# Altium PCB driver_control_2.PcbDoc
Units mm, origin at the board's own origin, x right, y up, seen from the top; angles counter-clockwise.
Board outline 75 x 80 mm, 2 copper layers (Top Layer, Bottom Layer); 60 components, 54 nets, 275 pads, 69 vias.
Unrouted connection lines stored in the file: 1.
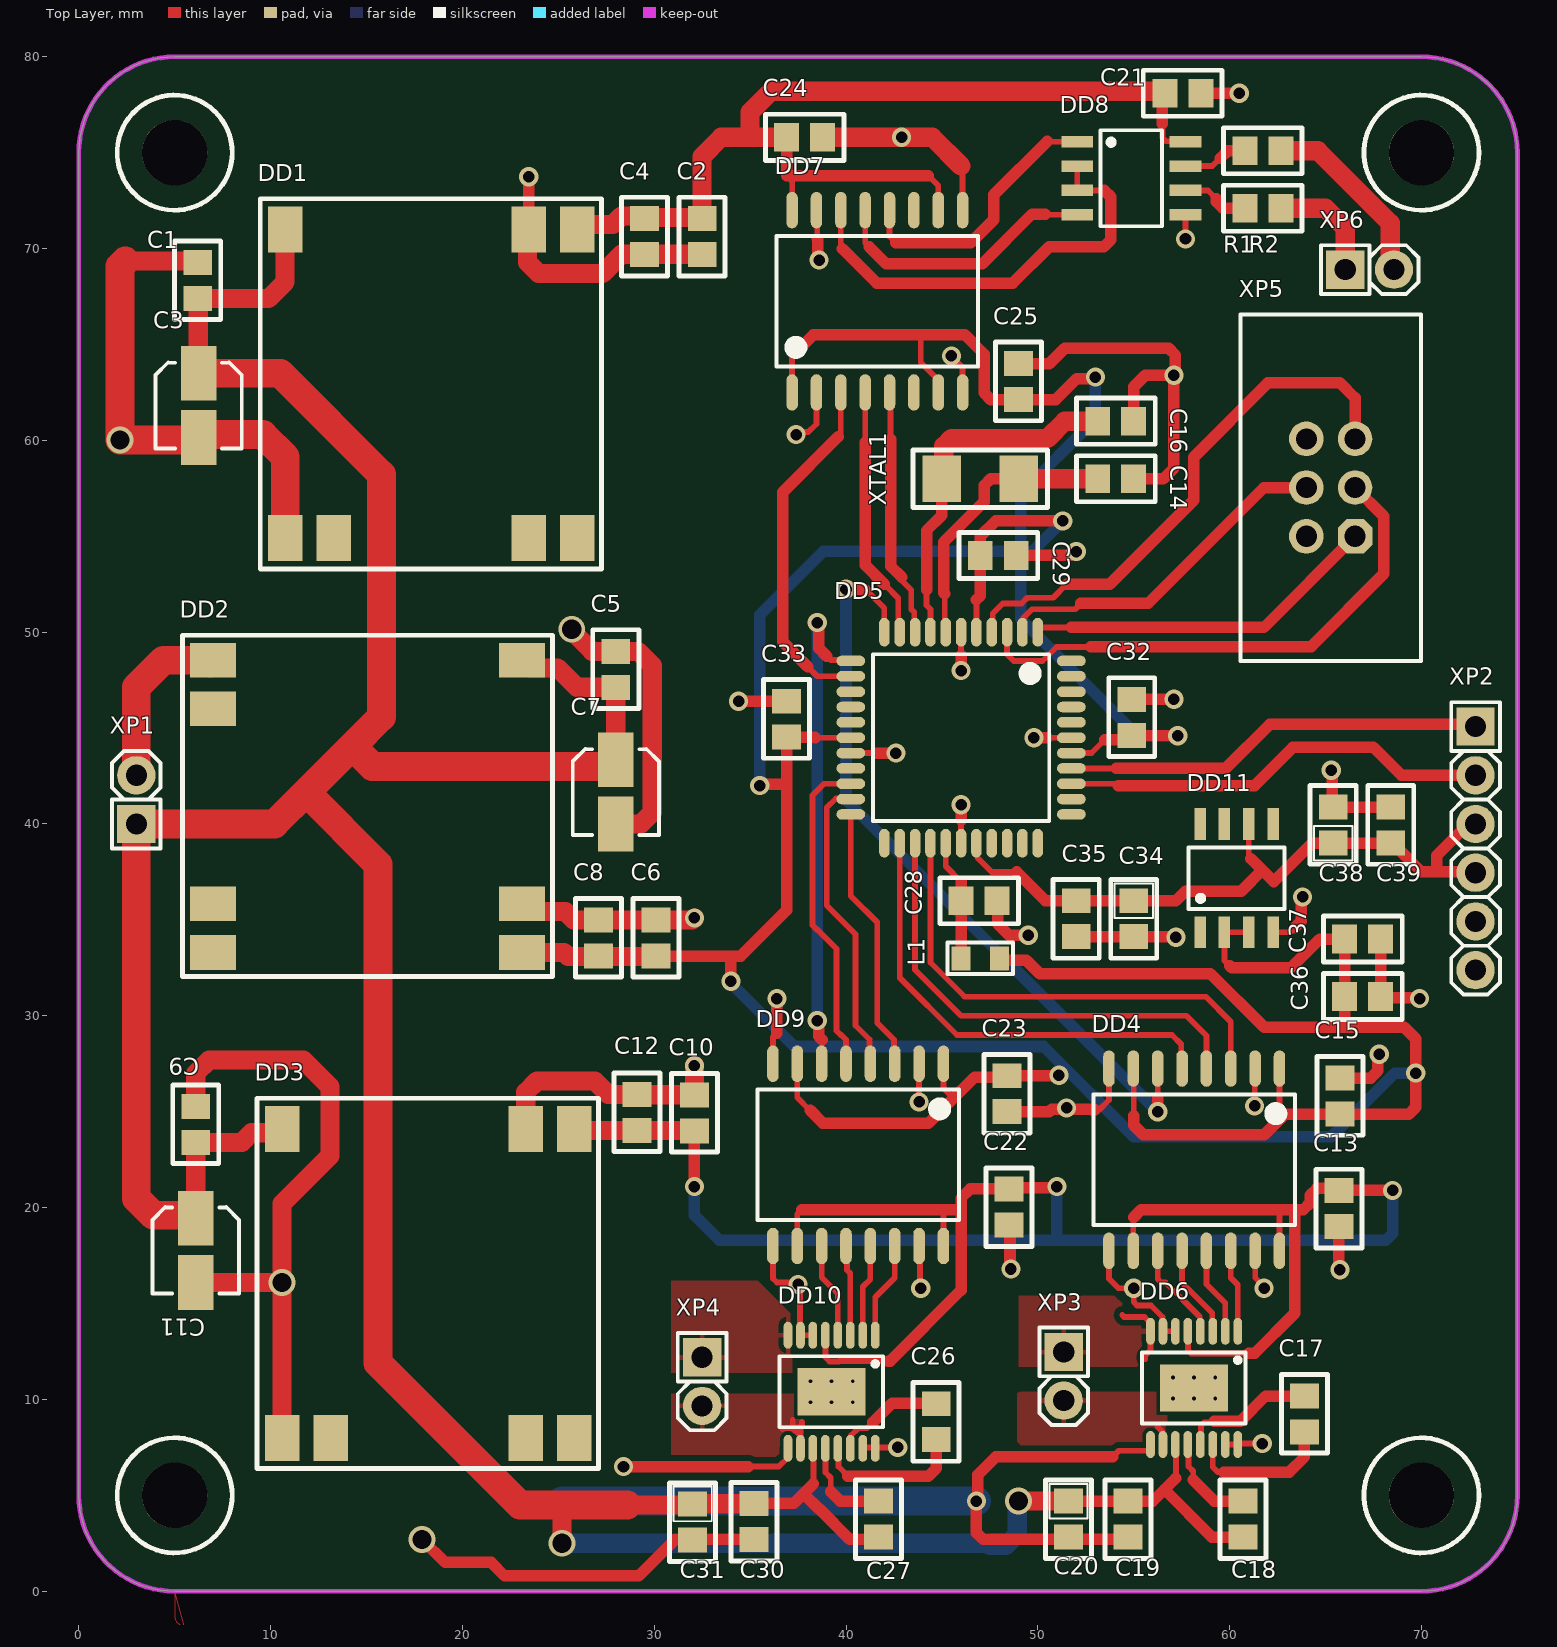
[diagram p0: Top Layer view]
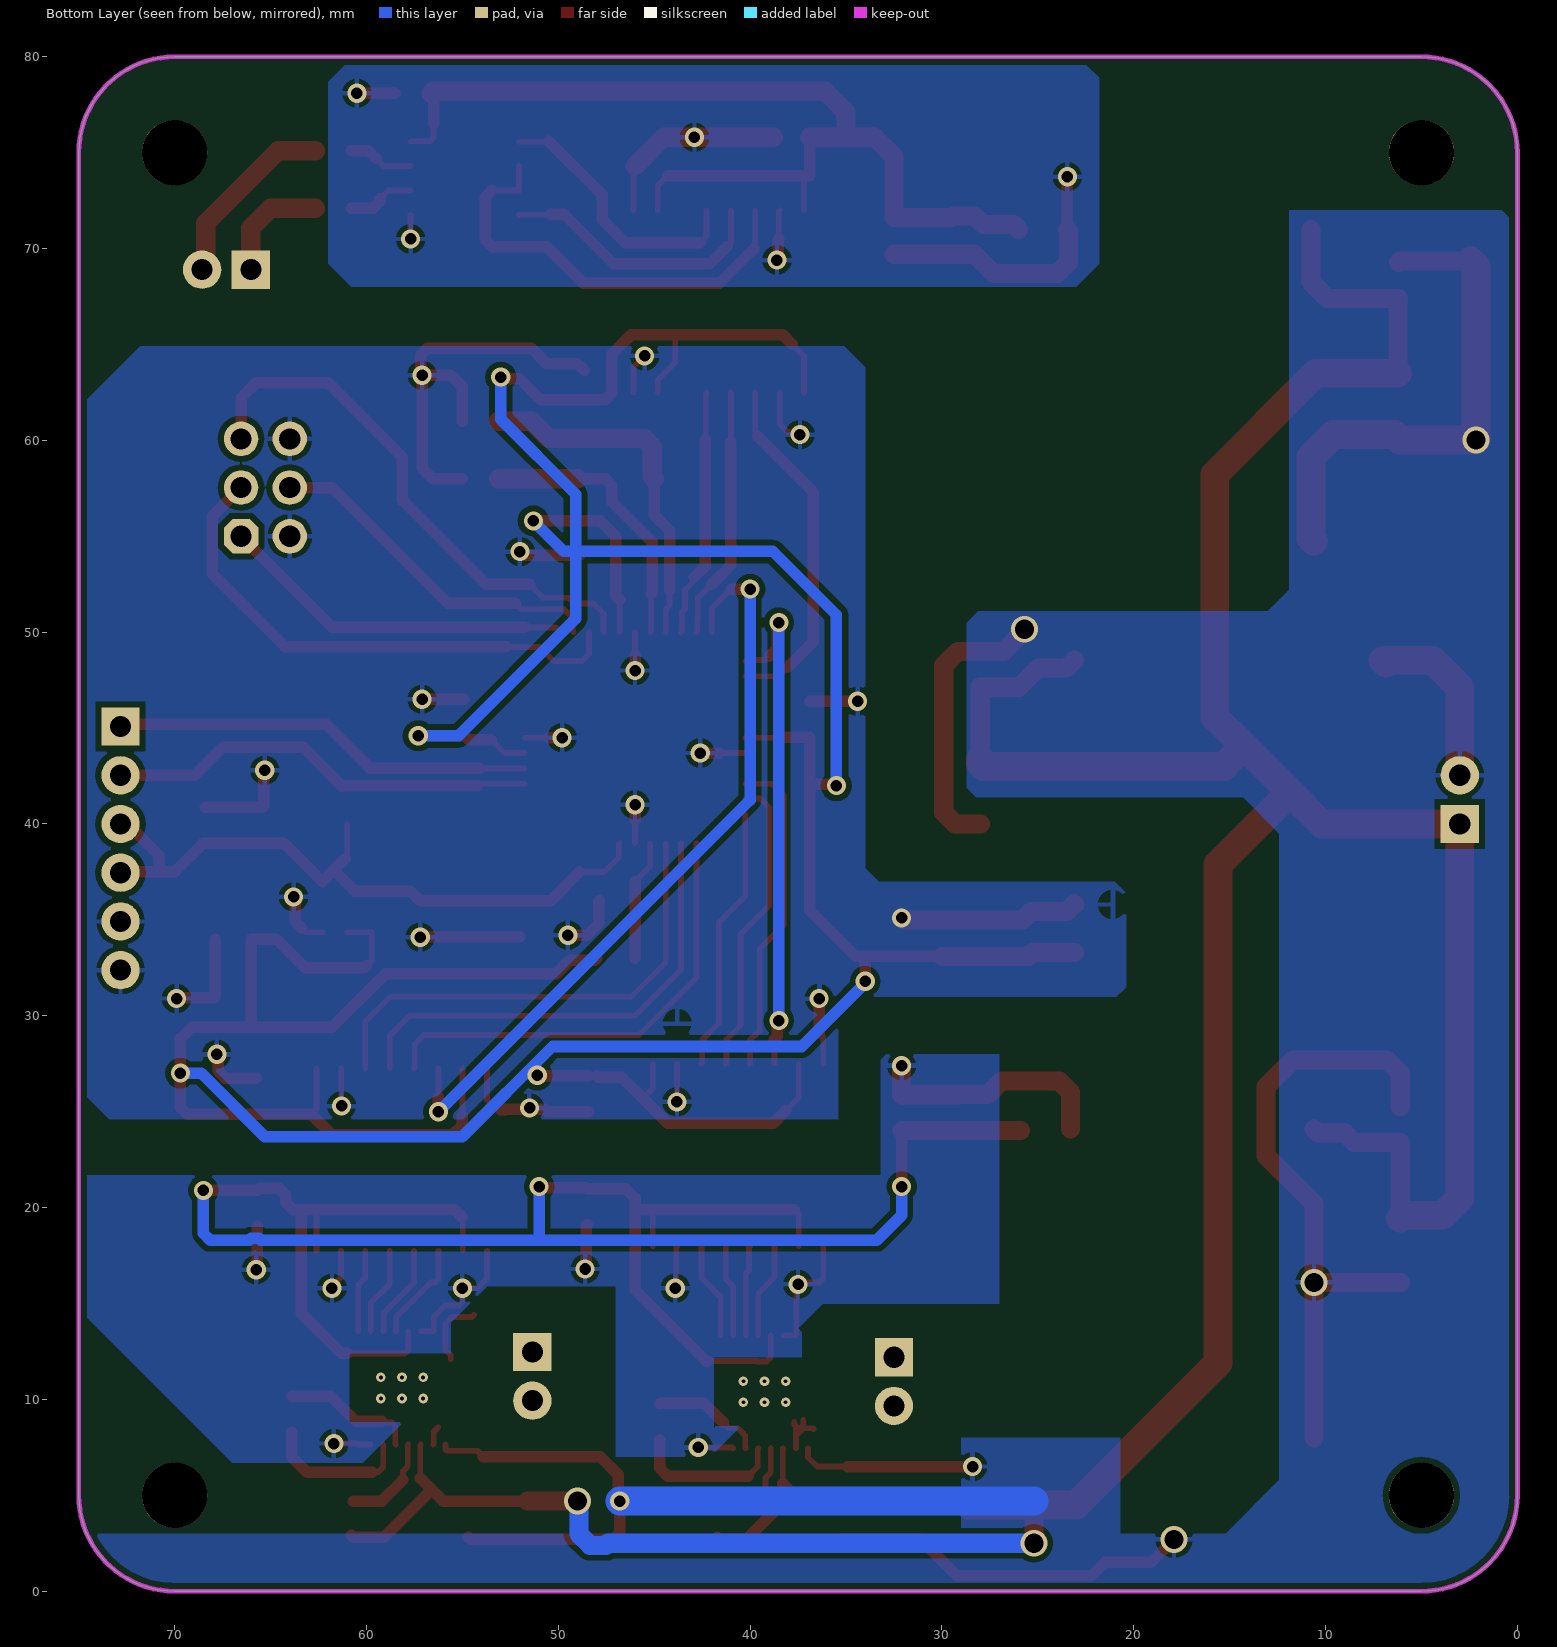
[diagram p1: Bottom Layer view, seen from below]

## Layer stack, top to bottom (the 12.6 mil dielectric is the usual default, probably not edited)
Top Solder: solder mask 0.0102, Solder Resist, Dk 3.5
Top Layer: signal copper 0.0356
Dielectric 1: dielectric 0.32, FR-4, Dk 4.8
Bottom Layer: signal copper 0.0356
Bottom Solder: solder mask 0.0102, Solder Resist, Dk 3.5

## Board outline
0,5 ccw(c5,5) 5,0 70,0 ccw(c70,5) 75,5 75,9 75,75 ccw(c70,75) 70,80 5,80 ccw(c5,75) 0,75

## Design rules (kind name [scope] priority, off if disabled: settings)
Clearance Clearance_2 [All] p1: gap=0.3 ignorepadtopadclearanceinfootprint=FALSE except(0.2: Arc-SMDPad Arc-THPad Track-SMDPad Track-THPad SMDPad-SMDPad SMDPad-THPad SMDPad-Via SMDPad-Fill SMDPad-Poly SMDPad-Region SMDPad-Text SMDPad-Hole)
HoleSize [All] p1: absolutevalues=TRUE maxlimit=5 minlimit=0.5 maxpercent=80.000 minpercent=20.000
HoleToHoleClearance [All] p1: gap=0.3 allowstackedmicrovias=TRUE
PolygonConnect [All] p1: connectstyle=Relief reliefconductorwidth=0.254 reliefentries=4 polygonreliefangle="90 Angle" airgapwidth=0.254
RoutingVias [All] p1: holewidth=0.6 width=1 viastyle="Through Hole" minholewidth=0.6 minwidth=1 maxholewidth=0.6 maxwidth=1
SilkToSilkClearance [All] p1: silktosilkclearance=0.2
SilkToSolderMaskClearance [IsPad] p1: minsilkscreentomaskgap=0.2 clearancetoexposedcopper=TRUE
SolderMaskExpansion [All] p1: expansion=0.102 istentingtop=FALSE
Width [All] p1: maxlimit=4 minlimit=0.2 preferedwidth=0.3
26 further rules are at their usual default settings.

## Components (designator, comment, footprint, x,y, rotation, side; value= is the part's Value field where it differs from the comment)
C1 "10мкФ" Capacitor_0805 6.2,67.4 r90 top
C2 "0.1мкФ" Capacitor_0805 32.5,71.575 r270 top
C3 "100мкФ" CAPAE4643X46M 6.25,63.5 r270 top
C4 "10мкФ" Capacitor_0805 29.5,71.575 r270 top
C5 "10мкФ" Capacitor_0805 28,47.125 r90 top
C6 "0.1мкФ" Capacitor_0805 30.1,33.125 r90 top
C7 "100мкФ" CAPAE4643X46M 28,43.35 r270 top
C8 "10мкФ" Capacitor_0805 27.1,33.125 r90 top
C9 "10мкФ" Capacitor_0805 6.1,23.4 r90 top
C10 "0.1мкФ" Capacitor_0805 32.1,24 r90 top
C11 "100мкФ" CAPAE4643X46M 6.1,19.45 r270 top
C12 "10мкФ" Capacitor_0805 29.1,24.025 r90 top
C13 "0.1мкФ" Capacitor_0805 65.7,20.9 r270 top
C14 "22пкФ" Capacitor_0805 53.125,58 r0 top
C15 "0.1мкФ" Capacitor_0805 65.75,24.875 r90 top
C16 "22пкФ" Capacitor_0805 53.125,61 r0 top
C17 "22пкФ" Capacitor_0805 63.9,8.3 r90 top
C18 "0.1мкФ" Capacitor_0805 60.7,4.7 r270 top
C19 "0.1мкФ" Capacitor_0805 54.7,4.7 r270 top
C20 "1мкФ" Capacitor_tant_0805 51.6,4.7 r270 top
C21 "0.1мкФ" Capacitor_0805 58.5,78.1 r180 top
C22 "0.1мкФ" Capacitor_0805 48.5,20.975 r270 top
C23 "0.1мкФ" Capacitor_0805 48.4,26.875 r270 top
C24 "0.1мкФ" Capacitor_0805 36.9,75.8 r0 top
C25 "0.1мкФ" Capacitor_0805 49,62.125 r90 top
C26 "22пкФ" Capacitor_0805 44.7,9.775 r270 top
C27 "0.1мкФ" Capacitor_0805 41.7,4.7 r270 top
C28 "0.1мкФ" Capacitor_0805 46,36 r0 top
C29 "0.1мкФ" Capacitor_0805 47,54 r0 top
C30 "0.1мкФ" Capacitor_0805 35.2,4.575 r270 top
C31 "1мкФ" Capacitor_tant_0805 32,4.55 r270 top
C32 "0.1мкФ" Capacitor_0805 54.9,44.625 r90 top
C33 "0.1мкФ" Capacitor_0805 36.9,44.525 r90 top
C34 "1мкФ" Capacitor_tant_0805 55,36 r270 top
C35 "0.1мкФ" Capacitor_0805 52,36 r270 top
C36 "10мкФ" Capacitor_0805 66,31 r0 top
C37 "0.1мкФ" Capacitor_0805 66,34 r0 top
C38 "1мкФ" Capacitor_tant_0805 65.4,39 r90 top
C39 "0.1мкФ" Capacitor_0805 68.4,39 r90 top
DD1 "TMR-1-2411SM" TMR1SM_SMD 10.76,54.9 r270 top
DD2 "TDR-2-2411SM" TMR1SM_SMD 7,48.54 r180 top
DD3 "TMR-1-2411SM" TMR1SM_SMD 10.6,8 r270 top
DD4 "ADuM1401" ADUM_SOIC 62.6,27.25 r270 top
DD5 "ATMEGA16-8UA" ATMEGA16-44A 50,50 r270 top
DD6 "DRV8874" DRV8874_TSOP127P600-8N 60.425,13.55 r270 top
DD7 "ADuM1301" ADUM_SOIC 37.19,62.5 r90 top
DD8 "ADM485" "SOIC_N8 (REF198, ADM485)" 52.05,75.57 r0 top
DD9 "ADuM1401" ADUM_SOIC 45.08,27.5 r270 top
DD10 "DRV8874" DRV8874_TSOP127P600-8N 41.525,13.35 r270 top
DD11 "REF198" "SOIC_N8 (REF198, ADM485)" 58.46,34.35 r90 top
L1 "Fixed inductor, 10мкГн, ±20%, 0805, 100mA, -55...+125°C" "IND: 0805" 47,33 r180 top value=10мкГн
R1 "120 Ом" resistor_0805 62.675,72.1 r180 top
R2 "120 Ом" resistor_0805 62.675,75.1 r180 top
XP1 "PLS-2" "CON: PLS-2" 3,41.27 r90 top
XP2 "Connector, 6pin, 2.54mm, 500VAC, 3A" "CON: PLS-6" 72.821,38.73 r270 top
XP3 "PLS-2" "CON: PLS-2" 51.35,11.205 r270 top
XP4 "PLS-2" "CON: PLS-2" 32.5,10.93 r270 top
XP5 "Connector, 6pin, 2.54mm, 500VAC, 3A" "CON: IDC-6MS" 65.27,57.54 r90 top
XP6 "PLS-2" "CON: PLS-2" 67.3,68.9 r0 top
XTAL1 "8Мгц" Z_0503 45,58 r0 top

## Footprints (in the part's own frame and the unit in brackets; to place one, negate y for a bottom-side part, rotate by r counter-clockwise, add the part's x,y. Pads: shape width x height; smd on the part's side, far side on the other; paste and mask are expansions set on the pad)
ADUM_SOIC [mm]
  oval 1.9x0.6 smd: 1(0,0) 2(0,-1.27) 3(0,-2.54) 4(0,-3.81) 5(0,-5.08) 6(0,-6.35) 7(0,-7.62) 8(0,-8.89) 9(9.5,-8.89) 10(9.5,-7.62) 11(9.5,-6.35) 12(9.5,-5.08) 13(9.5,-3.81) 14(9.5,-2.54) 15(9.5,-1.27) 16(9.5,0)
  silkscreen extent 1.35,-9.69 8.15,0.8
ATMEGA16-44A [mm]
  oval 1.5x0.55 smd: 1(0,0) 2(0,-0.8) 3(0,-1.6) 4(0,-2.4) 5(0,-3.2) 6(0,-4) 7(0,-4.8) 8(0,-5.6) 9(0,-6.4) 10(0,-7.2) 11(0,-8) 23(11,-8) 24(11,-7.2) 25(11,-6.4) 26(11,-5.6) 27(11,-4.8) 28(11,-4) 29(11,-3.2) 30(11,-2.4) 31(11,-1.6) 32(11,-0.8) 33(11,0)
  oval 0.55x1.5 smd: 12(1.5,-9.75) 13(2.3,-9.75) 14(3.1,-9.75) 15(3.9,-9.75) 16(4.7,-9.75) 17(5.5,-9.75) 18(6.3,-9.75) 19(7.1,-9.75) 20(7.9,-9.75) 21(8.7,-9.75) 22(9.5,-9.75) 34(9.5,1.75) 35(8.7,1.75) 36(7.9,1.75) 37(7.1,1.75) 38(6.3,1.75) 39(5.5,1.75) 40(4.7,1.75) 41(3.9,1.75) 42(3.1,1.75) 43(2.3,1.75) 44(1.5,1.75)
  silkscreen extent 1.15,-8.6 9.85,0.6, body extent 1.15,-8.6 9.85,0.6, height 1.2
Capacitor_0805 [mm]
  rect 1.3x1.5 smd: 1(0,0) 2(1.875,0)
  silkscreen extent -1.1,-1.2 3,1.2
Capacitor_tant_0805 [mm]
  rect 1.3x1.5 smd: 1(0,0) 2(1.875,0)
  silkscreen extent -1.1,-1.2 3,1.2
CAPAE4643X46M [mm] "Aluminum Electrolytic Capacitor, Body 4,30x4,30x4,60mm, IPC Low Density"
  rect 2.85x1.85 smd: 1(0,0) 2(3.35,0)
  silkscreen extent -0.58,-2.25 3.93,2.25
"CON: IDC-6MS" [mm] "IDC-6MS 6 pin PCB-mount connector"
  oct 1.8x1.8 hole 1.1: 1(-2.54,-1.27)
  round 1.8 hole 1.1: 2(-2.54,1.27) 3(0,-1.27) 4(0,1.27) 5(2.54,-1.27) 6(2.54,1.27)
  round 0.5 on Top Overlay: ""(-9.6,-4.5)
  round 0.5 on Mech1: ""(-8.4,-4)
  silkscreen extent -9.05,-4.7 9.03,4.7, body extent -8.89,-4.55 8.87,4.55, height 9
"CON: PLS-2" [mm]
  rect 2x2 hole 1.1: 1(-1.27,0)
  round 2 hole 1.1: 2(1.27,0)
  silkscreen extent -2.54,-1.27 2.54,1.27, body extent -2.57,-1.28 2.51,1.26, height 8.54
"CON: PLS-6" [mm]
  rect 2x2 hole 1.1: 1(-6.35,0)
  round 2 hole 1.1: 2(-3.81,0) 3(-1.27,0) 4(1.27,0) 5(3.81,0) 6(6.35,0)
  silkscreen extent -7.62,-1.27 7.62,1.27, body extent -7.62,-1.27 7.62,1.27, height 8.54
DRV8874_TSOP127P600-8N [mm]
  oval 1.4x0.45 smd: 1(0,0) 2(0,-0.65) 3(0,-1.3) 4(0,-1.95) 5(0,-2.6) 6(0,-3.25) 7(0,-3.9) 8(0,-4.55) 9(5.9,-4.55) 10(5.9,-3.9) 11(5.9,-3.25) 12(5.9,-2.6) 13(5.9,-1.95) 14(5.9,-1.3) 15(5.9,-0.65) 16(5.9,0)
  rect 2.46x3.55 smd: 17(2.95,-2.275)
  silkscreen extent 1.1,-5 4.8,0.4
"IND: 0805" [mm]
  rect 1x1.25 smd: 1(-1,0) 2(1,0)
  silkscreen extent -1.7,-0.82 1.7,0.82, body extent -1,-0.62 1,0.63, height 0.85
resistor_0805 [mm] "ЧИП-резистор типоразмера 0805"
  rect 1.3x1.5 smd: 0(0,0) 1(1.875,0)
  silkscreen extent -1.1,-1.2 3,1.2
"SOIC_N8 (REF198, ADM485)" [mm] "SOIC, 8-Leads, Body 4,90x3,90mm, Pitch 1,27mm, IPC Medium Density"
  rect 1.65x0.6 smd: 1(0,0) 2(0,-1.27) 3(0,-2.54) 4(0,-3.81) 5(5.65,-3.81) 6(5.65,-2.54) 7(5.65,-1.27) 8(5.65,0)
  silkscreen extent 1.22,-4.41 4.43,0.6
TMR1SM_SMD [mm]
  rect 2.4x1.8 smd: 1(0,0) 2(0,2.54) 6(0,12.7) 7(0,15.24) 8(-16.1,15.24) 9(-16.1,12.7) 14(-16.1,0)
  silkscreen extent -17.7,-1.3 1.6,16.5
Z_0503 [mm]
  rect 2x2.4 smd: 1(0,0) 2(4,0)
  silkscreen extent -1.5,-1.5 5.5,1.5

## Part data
C1 C2 C4 C5 C6 C8 C9 C10 C12 C13 C14 C15 C16 C17 C18 C19 C21 C22 C23 C24 C25 C26 C27 C28 C29 C30 C32 C33 C35 C36 C37 C39: library part Capacity_0805
C3 C7 C11: library part Capacity_electrolity_polar_0805, "electrolity capacitor"
C20 C31 C34 C38: library part Capacity_tantal_0805, "tanral capacitor"
DD5: library part ATMEGA16-44A
L1: library part Inductor_0805, Manufacturer="Murata Electronics", MaxCurrent=100mA, Package=0805, PartNumber=LQM21FN100M70L, Temperature=-55...+125°C, Tolerance=±20%, TypeInductor="Fixed inductor"
R1 R2: library part Resistor_0805
XP1 XP6: "https://www.chipdip.ru/product/wf-2r"
XP2: library part PLS-6, CurrentMax=3A, Manufacturer=Connfly, VoltageMax=500VAC
XP3 XP4: library part PLS-2-1
XP5: library part IDC-6, CurrentMax=3A, Manufacturer=Connfly, PartNumber=PLS-6, VoltageMax=500VAC
XTAL1: library part resonstor

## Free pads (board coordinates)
  round 3.4 hole 3.4 unplated: 9(5,5) 9(5,75) 9(70,5) 9(70,75)

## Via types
v1: diameter 1, hole 0.6, Top Layer to Bottom Layer, 51 vias
v2: diameter 0.5, hole 0.2, Top Layer to Bottom Layer, 12 vias
v3: diameter 1.4, hole 1, Top Layer to Bottom Layer, 6 vias

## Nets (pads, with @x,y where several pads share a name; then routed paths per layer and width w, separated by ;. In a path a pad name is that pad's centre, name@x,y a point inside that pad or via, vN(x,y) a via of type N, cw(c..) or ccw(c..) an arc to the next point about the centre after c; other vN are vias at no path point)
+5B: C6.1 C8.1 C15.1 C23.1 C25.1 C29.1 C32.1 C33.1 C36.1 C37.1 DD2.8 DD4.1 DD4.7 DD5.5 DD5.17 DD5.38 DD7.1 DD7.7 DD9.1 DD9.7 DD11.2 DD11.3 L1.1 | length 243.4
  Top Layer w0.3: DD7.1 37.19,64.39 37.8,65 ; DD9.7 37.46,25.74 38.13,25.07 ; 38.4,44.5 DD5.17 ; 44,65.5 43.9,65.4 43.9,64.06 44.81,63.15 DD7.7 ; DD9.1 45.08,26.22 45.55,25.75 45.55,25.65 ; DD5.5 46.8,51.7 ; DD5.38 52.8,43.7 53.5,44.4 ; DD4.7 55,27.23 55,24.8 ; 60,32.6 59.73,32.87 DD11.2 DD11.3 ; DD4.1 62.6,25.15 62.875,24.875
  Top Layer w0.6: C6.1@30.1,33.1 34.5,33.1 36.9,35.5 36.9,42.1 ; v1(34,31.8) 34,33.1 ; v1(35.5,42) 35.577,42.077 36.877,42.077 36.9,42.1 ; 37.8,65 38.3,65.5 44,65.5 46.2,65.5 47.2,64.5 47.2,62.476 47.551,62.125 C25.1 50.925,62.125 52.023,63.223 52.923,63.223 v1(53,63.3) ; 38.13,25.07 38.8,24.4 44.3,24.4 45.55,25.65 46.7,26.8 47.925,26.8 C23.1@48,26.875 ; 38.4,44.5 38.375,44.525 C33.1 36.9,42.1 ; 46.8,51.7 47,51.9 C29.1 47,55 47.8,55.8 v1(51.3,55.8) ; L1.1 48.1,32.9 49.4,32.9 50.1,32.2 59,32.2 61.8,29.4 66,29.4 ; C23.1 48.413,26.888 51.088,26.888 v1(51.1,26.9) ; 53.5,44.4 54.675,44.4 C32.1 54.913,44.612 57.288,44.612 v1(57.3,44.6) ; 55,24.8 54.999,24.799 54.999,24.301 55.5,23.8 61.8,23.8 62.875,24.875 C15.1 69.349,24.875 69.7,25.226 69.7,28.8 69.1,29.4 66,29.4 ; 60,32.6 60.1,32.5 63.2,32.5 64.7,34 C37.1 C36.1 66,29.4
  Top Layer w1: DD2.8 25.3,33.3 25.5,33.1 C6.1@30,33.1
  Bottom Layer w0.6: v1@33.9,31.8 37.3,28.4 50.3,28.4 55,23.7 65.3,23.7 68.613,27.013 v1(69.7,27.013) ; v1(35.5,42) 35.5,50.9 38.811,54.211 49.1,54.211 ; v1(51.3,55.8) 49.711,54.211 49.1,54.211 ; v1(53,63.3) 53,61.1 49.1,57.2 49.1,54.211 ; v1(57.3,44.6) 55.2,44.6 49.1,50.7 49.1,54.211
+5B_DRV: C10.1 C12.1 C13.1 C22.1 DD3.8 DD4.10 DD4.16 DD6.5 DD9.10 DD9.16 DD10.5 | length 116.3
  Top Layer w0.3: DD9.10 37.46,19.66 37.7,19.9 ; DD10.5 38.925,12.2 39.145,11.98 39.617,11.98 39.637,12 42.2,12 ; DD9.16 45.08,19.9 ; DD4.10 54.98,19.48 55,19.5 ; DD6.5 57.825,12.576 58.001,12.4 61,12.4 ; 62.5,19.9 62.6,19.8 DD4.16
  Top Layer w0.6: DD3.8 DD3.8@25.915,24.025 ; C12.1 C12.1@29.112,24.012 ; C10.1@32.087,24.012 C10.1 v1(32.1,21.1) ; 37.7,19.9 45.08,19.9 46,19.9 ; 42.2,12 42.3,12 46,15.7 46,19.9 ; v1(51,21.1) 50.938,21.038 48.563,21.038 C22.1 46.475,20.975 46,20.5 46,19.9 ; 55,19.5 55.4,19.9 62.5,19.9 63.4,19.9 ; 61,12.4 61.3,12.4 63.4,14.5 63.4,19.9 ; v1(68.5,20.9) C13.1 65.6,21 64.551,21 64.2,20.649 64.2,20.251 63.849,19.9 63.4,19.9
  Top Layer w1: DD3.8@25.915,24.025 C12.1 ; C12.1@29.112,24.012 C10.1@32.087,24.012
  Bottom Layer w0.6: v1(32.1,21.1) 32.1,19.6 33.4,18.3 51,18.3 ; v1(51,21.1) 51,18.3 ; v1(68.5,20.9) 68.5,18.651 68.149,18.3 66.1,18.3 66,18.4 65.6,18.4 65.5,18.3 51,18.3
+5B_RS: C2.1 C4.1 C21.2 C24.1 DD1.8 DD7.10 DD7.16 DD8.8 | length 55.2
  Top Layer w0.3: 36.9,73.8 37.2,73.5 37.2,72.01 DD7.16 ; 44.3,73.8 44.81,73.29 DD7.10 ; 56.5,76.5 56.5,75.776 56.676,75.6 57.67,75.6 DD8.8
  Top Layer w0.6: C24.1 36.9,73.8 44.3,73.8 ; 56.5,76.5 56.5,77.975 C21.2
  Top Layer w1: DD1.8 26.25,71.25 27.85,71.25 28.3,71.7 29.425,71.7 29.5,71.625 32.5,71.625 32.5,74.8 33.5,75.8 35,75.8 ; C24.1 35,75.8 ; C21.2 56.525,78.2 36.086,78.2 35,77.114 35,75.8
+27B: C1.1 C3.1 C5.1 C7.1 C9.1 C11.1 C18.2 C19.1 C20.1 C27.2 C30.1 C31.1 DD1.14 DD2.14 DD3.14 DD6.11 DD10.11 XP1.1 | length 214.4
  Top Layer w0.3: DD10.11 38.3,7.425 38.3,5.6 ; DD6.11 57.2,7.625 57.2,5.9
  Top Layer w0.6: C30.1 37.275,4.575 37.788,5.088 ; 38.3,5.6 37.788,5.088 ; C27.2 41.575,2.7 40.2,2.7 38.6,4.3 38.575,4.3 37.788,5.088 ; C20.1 C19.1 56,4.7 56.6,5.3 ; 57.2,5.9 56.6,5.3 ; C18.2@60.8,2.925 C18.2 59.075,2.825 56.6,5.3
  Top Layer w1: C11.1 C9.1 8.5,23.4 9,23.9 10.4,23.9 DD3.14 ; C3.1 6.225,63.525 6.225,67.375 C1.1 9.9,67.4 10.76,68.26 DD1.14 ; DD2.14 23.5,48.14 24.96,48.14 25.975,47.125 C5.1 C7.1 ; v3(25.2,2.5) 25.2,4.5 ; 28.6,4.5 31.95,4.5 C31.1 32.013,4.562 35.187,4.562 C30.1 ; v3(49,4.7) C20.1
  Top Layer w1.5: C11.1 5.95,19.6 3.879,19.6 3,20.479 XP1.1 10.2,40 11.9,41.7 ; C3.1 10.5,63.5 15.779,58.221 15.779,45.579 14.25,44.05 ; C7.1 28,43.175 27.825,43 15.3,43 14.25,44.05 ; 28.6,4.5 25.2,4.5 23,4.5 15.6,11.9 15.6,37.9 11.9,41.6 11.9,41.7 ; 11.9,41.7 14.25,44.05
  Bottom Layer w1: v3(25.2,2.5) 47.4,2.5 47.509,2.391 48.338,2.391 48.923,2.977 48.923,4.623 v3(49,4.7)
AREF: C34.1 C35.1 C38.1 C39.1 DD5.29 DD11.6 XP2.3 XP2.4 | length 36.3
  Top Layer w0.3: DD5.29 46.848,38.952 46.848,38.252 47.6,37.5 48.9,37.5 ; DD11.6 61,38.3 61.1,38.2
  Top Layer w0.6: 48.9,37.5 50.4,36 C35.1 C34.1 57.2,36 57.7,36.5 60.6,36.5 61.7,37.6 ; 61.1,38.2 61.7,37.6 ; XP2.4 72.761,37.52 70.8,37.52 ; XP2.3 72.442,40 70.8,38.358 70.8,37.52 ; 61.7,37.6 62.3,37 64.3,39 C38.1 C39.1 68.5,39 69.98,37.52 70.8,37.52
DRV11: DD5.22 DD9.3 | length 13.9
  Top Layer w0.3: DD5.22 40.25,36.25 41.625,34.875 41.625,29.625 42.498,28.752 42.498,27.542 DD9.3
DRV12: DD5.21 DD9.4 | length 15.8
  Top Layer w0.3: DD5.21 40.218,41.332 39.473,41.332 39,40.859 39,35.75 40.5,34.25 40.5,29.5 41.228,28.772 41.228,27.542 DD9.4
DRV13: DD5.20 DD9.5 | length 17
  Top Layer w0.3: DD9.5 40,28.75 39.75,29 39.723,29 39.5,29.223 39.5,33.5 38.5,34.5 38.473,34.5 38.25,34.723 38.25,41.5 38.85,42.1 DD5.20
DRV14: DD5.12 DD9.6 | length 26.4
  Top Layer w0.3: DD9.6 38.73,28.73 38.75,28.75 ; 39,48.75 39.202,48.548 40.202,48.548 DD5.12
  Top Layer w0.6: v1(38.5,29.75) 38.577,29.673 38.577,28.923 38.75,28.75 ; v1(38.5,50.5) 38.577,50.423 38.577,49.173 39,48.75
  Bottom Layer w0.6: v1(38.5,29.75) v1(38.5,50.5)
DRV21: DD4.3 DD5.26 | length 25.6
  Top Layer w0.3: DD5.26 44.4,32.781 46.181,31 58.75,31 60.06,29.69 DD4.3
DRV22: DD4.4 DD5.25 | length 24.9
  Top Layer w0.3: DD5.25 43.6,32.4 46,30 57.75,30 58.79,28.96 DD4.4
DRV23: DD4.5 DD5.24 | length 24.4
  Top Layer w0.3: DD5.24 42.8,31.987 45.787,29 57,29 57.478,28.522 57.478,27.292 DD4.5
DRV24: DD4.6 DD5.11 | length 39.9
  Top Layer w0.3: 40.989,52.239 41.011,52.239 42,51.25 DD5.11 ; 56.25,25.75 DD4.6
  Top Layer w0.6: v1(40,52.25) 40.011,52.239 40.989,52.239 ; v1(56.25,25) 56.25,25.75
  Bottom Layer w0.6: v1(40,52.25) 40,41.25 v1(56.25,25)
ENB: DD5.13 DD7.3 | length 18.6
  Top Layer w0.3: 38,48.2 38.5,47.7 DD5.13 ; 39.6,60.2 39.73,60.33 DD7.3
  Top Layer w0.6: 38,48.2 36.7,49.5 36.7,57.3 39.6,60.2
GND: C1.2 C3.2 C5.2 C7.2 C9.2 C11.2 C19.2 C20.2 C30.2 C31.2 DD1.1 DD2.1 DD3.1 DD6.9 DD10.9 XP1.2 | length 155.2
  Top Layer w0.3: 34.9,6.5 36.495,6.5 36.975,6.98 DD10.9 ; 53.9,7 54.225,7.325 55.806,7.325 55.875,7.394 DD6.9
  Top Layer w0.6: v3(17.9,2.7) 19.1,1.5 21.5,1.5 22.2,0.8 29.2,0.8 31.1,2.7 C30.2 ; v1(28.4,6.5) 34.9,6.5 ; 53.9,7 47.8,7 46.877,6.077 46.877,4.777 v1(46.8,4.7) 46.8,3.051 47.151,2.7 54.575,2.7 C19.2
  Top Layer w1: 2.425,69.35 6.125,69.35 C1.2 ; C11.2 v3(10.6,16.1) ; C9.2 6.1,27 6.8,27.7 11.7,27.7 13.1,26.3 13.1,22.7 10.6,20.2 v3(10.6,16.1) ; DD3.1 v3(10.6,16.1) ; v3(25.7,50.15) 25.7,50.075 26.775,49 C5.2 29.164,49 29.9,48.264 29.9,40.6 29.3,40 C7.2
  Top Layer w1.5: 2.425,69.35 2.15,69.075 v3(2.15,60.025) 6.125,60.025 C3.2 6.4,60.3 9.6,60.3 10.76,59.14 DD1.1 DD1.1@10.61,54.75 ; XP1.2 3,47.125 4.415,48.54 DD2.1 DD2.1@6.85,48.39
  Bottom Layer w1.5: 25.2,4.7 v1(46.8,4.7)
MISO: DD5.2 XP5.4 | length 18.3
  Top Layer w0.3: DD5.2 49.248,50.048 49.248,50.748 49.7,51.2 51.95,51.2 52.25,51.5
  Top Layer w0.6: 52.25,51.5 55.75,51.5 61.79,57.54 XP5.4
MOSI: DD5.1 XP5.1 | length 18.7
  Top Layer w0.3: DD5.1 50,50.135 50.115,50.25 51.75,50.25
  Top Layer w0.6: 51.75,50.25 61.79,50.25 XP5.1
NetC17_1: C17.1 DD6.14 | length 7.7
  Top Layer w0.3: DD6.14 59.125,6.475 59.4,6.2 59.7,6.2
  Top Layer w0.6: 59.7,6.2 63.1,6.2 63.9,7 C17.1
NetC17_2: C17.2 DD6.13 | length 7
  Top Layer w0.3: DD6.13 58.504,7.679 58.504,8.628 58.676,8.8 59.15,8.8 59.2,8.85
  Top Layer w0.6: 59.2,8.85 60.55,8.85 61.875,10.175 C17.2
NetC18_1: C18.1 DD6.12 | length 5
  Top Layer w0.3: DD6.12 57.854,7.621 57.854,6.506 58.1,6.259 58.1,5.8
  Top Layer w0.6: 58.1,5.8 59.2,4.7 C18.1
NetC26_1: C26.1 DD10.14 | length 5.8
  Top Layer w0.3: DD10.14 40.254,7.479 40.254,8.117 40.637,8.5 41.1,8.5 41.4,8.8
  Top Layer w0.6: 41.4,8.8 42.4,9.8 44.675,9.8 C26.1
NetC26_2: C26.2 DD10.13 | length 7.9
  Top Layer w0.3: DD10.13 39.604,7.421 39.604,6.496 40.1,6
  Top Layer w0.6: 40.1,6 44.3,6 44.7,6.4 C26.2
NetC27_1: C27.1 DD10.12 | length 5.1
  Top Layer w0.3: DD10.12 38.925,6.19 39.2,5.915 39.2,5.2
  Top Layer w0.6: 39.2,5.2 39.7,4.7 C27.1
NetC28_1: C28.1 DD5.27 L1.2 | length 6.3
  Top Layer w0.3: DD5.27 45.2,37.8 46,37
  Top Layer w0.6: L1.2 C28.1 46,37
NetDD4_11: DD4.11 DD6.4 | length 5.3
  Top Layer w0.3: DD4.11 56.25,16.276 56.426,16.1 56.651,16.1 58.446,14.305 58.446,13.579 DD6.4
NetDD4_12: DD4.12 DD6.3 | length 4.9
  Top Layer w0.3: DD4.12 57.52,16.08 59.096,14.504 59.096,13.579 DD6.3
NetDD4_13: DD4.13 DD6.2 | length 4.6
  Top Layer w0.3: DD4.13 58.79,16.01 59.775,15.025 DD6.2
NetDD4_14: DD4.14 DD6.1 | length 4.4
  Top Layer w0.3: DD4.14 60.06,16.34 60.425,15.975 DD6.1
NetDD6_8: DD6.8 XP3.1 | length 3.6
  Top Layer w0.3: 54.4,14.4 54.5,14.3 55.559,14.3 55.875,13.984 DD6.8 55.875,12.575 55.6,12.3 55.6,12.1
NetDD6_10: DD6.10 XP3.2 | length 1
  Top Layer w0.3: 56.261,8.552 56.496,8.317 56.496,7.679 DD6.10
NetDD7_12: DD7.12 DD8.1 | length 14.3
  Top Layer w0.3: DD7.12 42.27,70.63 42.6,70.3 ; 50.5,75.6 50.53,75.57 DD8.1
  Top Layer w0.6: 42.6,70.3 46.5,70.3 47.7,71.5 47.7,72.8 50.5,75.6
NetDD7_13: DD7.13 DD8.4 | length 14.3
  Top Layer w0.3: DD7.13 41,70.3 41.2,70.1 ; 50.4,71.8 50.44,71.76 DD8.4
  Top Layer w0.6: 41.2,70.1 42.1,69.2 47.1,69.2 49.7,71.8 50.4,71.8
NetDD7_14: DD7.14 DD8.2 DD8.3 | length 23.1
  Top Layer w0.3: DD7.14 39.73,70.07 39.8,70 ; DD8.2 DD8.3 53.47,73.03
  Top Layer w0.6: 39.8,70 41.6,68.2 48.7,68.2 50.6,70.1 53.449,70.1 53.8,70.451 53.8,72.7 53.47,73.03
NetDD8_6: DD8.6 R1.1 | length 3.6
  Top Layer w0.3: DD8.6 58.87,73.03 59.3,72.6
  Top Layer w0.6: 59.3,72.6 59.3,72.451 59.651,72.1 R1.1
NetDD8_7: DD8.7 R2.1 | length 3.4
  Top Layer w0.3: DD8.7 59.1,74.3 59.5,74.7
  Top Layer w0.6: 59.5,74.7 59.9,75.1 R2.1
NetDD9_11: DD9.11 DD10.4 | length 5
  Top Layer w0.3: DD9.11 38.73,16.37 39.575,15.525 DD10.4
NetDD9_12: DD9.12 DD10.3 | length 4.7
  Top Layer w0.3: DD9.12 40.057,17.943 40.057,16.743 40.225,16.575 DD10.3
NetDD9_13: DD9.13 DD10.2 | length 4.8
  Top Layer w0.3: DD10.2 40.875,15.875 41.27,16.27 DD9.13
NetDD9_14: DD9.14 DD10.1 | length 5.1
  Top Layer w0.3: DD10.1 41.525,15.325 42.54,16.34 DD9.14
NetDD10_8: DD10.8 XP4.1
NetDD10_10: DD10.10 XP4.2 | length 3.6
  Top Layer w0.3: 36.686,8.449 36.737,8.5 37.213,8.5 37.596,8.117 37.596,7.479 DD10.10 37.625,8.625 37.7,8.7 37.7,8.82 ; 37.227,8.922 37.227,8.673 37.358,8.542
NetR1_0: R1.0 XP6.1 | length 6
  Top Layer w1: R1.0 65,72.1 66.03,71.07 XP6.1
NetR2_0: R2.0 XP6.2 | length 9.8
  Top Layer w1: R2.0 64.6,75.1 68.379,71.321 68.379,69.091 XP6.2
POT1: DD5.37 XP2.1 | length 22.1
  Top Layer w0.3: DD5.37 54.1,42.9
  Top Layer w0.6: 54.1,42.9 59.8,42.9 62.1,45.2 72.701,45.2 XP2.1
POT2: DD5.36 XP2.2 | length 22.5
  Top Layer w0.3: DD5.36 54.1,42.1 54.2,42
  Top Layer w0.6: 54.2,42 61.3,42 63,43.7 63.3,44 67.5,44 68.96,42.54 XP2.2
RST: DD5.4 XP5.5 | length 29
  Top Layer w0.3: DD5.4 47.648,50.048 47.648,50.972 48.176,51.5 49.151,51.5 49.451,51.8 50.8,51.8 51.5,52.5
  Top Layer w0.6: 51.5,52.5 53.75,52.5 58.125,56.875 58.125,59.125 62,63 65.75,63 66.54,62.21 XP5.5 XP5.5@66.31,60.31
RXD: DD5.9 DD7.5 | length 12.7
  Top Layer w0.3: DD7.5 42.315,62.455 42.315,60.085 42.345,60.055 ; 43,52.6 43.4,52.2 43.4,51.2 43.552,51.048 43.552,50.048 DD5.9
  Top Layer w0.6: 42.345,60.055 42.345,53.428 42.9,52.873
SCK: DD5.3 XP5.3 | length 27.9
  Top Layer w0.3: DD5.3 48.4,48.85 48.75,48.5 50.25,48.5 50.975,49.225 52.725,49.225 52.75,49.25
  Top Layer w0.6: 52.75,49.25 64.25,49.25 68.04,53.04 68.04,56.04 XP5.3
TXD: DD5.10 DD7.4 | length 13.2
  Top Layer w0.3: 41,59.9 DD7.4 ; 42,52.5 42.725,51.775 42.725,50.727 42.752,50.7 42.752,50.048 DD5.10
  Top Layer w0.6: 41,59.9 41,53.5 42,52.5
XT1: C14.1 DD5.7 XTAL1.2 | length 14.6
  Top Layer w0.3: 45.15,52 45.15,50.702 45.152,50.7 45.152,50.048 DD5.7
  Top Layer w0.6: 45.15,52 45.1,52.05 45.1,54.7 47.2,56.8 47.2,57.649 47.551,58 XTAL1.2
  Top Layer w1: XTAL1.2 C14.1
XT2: C16.1 DD5.8 XTAL1.1 | length 18.7
  Top Layer w0.3: 44.2,52.2 44.2,51.4 44.4,51.2 DD5.8
  Top Layer w0.6: 44.2,52.2 44.2,55.3 45,56.1 XTAL1.1
  Top Layer w1: XTAL1.1 45.1,58.1 45.1,59.7 45.5,60.1 50.5,60.1 51.4,61 C16.1
Общ: C6.2 C8.2 C14.2 C15.2 C16.2 C23.2 C25.2 C28.2 C29.2 C32.2 C33.2 C34.2 C35.2 C36.2 C37.2 C38.2 C39.2 DD2.9 DD4.2 DD4.8 DD5.6 DD5.18 DD5.28 DD5.39 DD7.2 DD7.8 DD9.2 DD9.8 DD11.4 XP2.5 XP2.6 XP5.2 XP5.6 | length 91.3
  Top Layer w0.3: DD9.8 36.19,28.89 36.4,29.1 ; v1(37.4,60.3) 37.534,60.434 38.034,60.434 38.46,60.86 DD7.2 ; DD5.18 41.6,43.7 ; DD9.2 DD9.2 43.811,25.514 v1(43.812,25.512) ; v1(45.5,64.4) 46.08,63.82 DD7.8 ; DD5.28 46,40.2 ; 46,48.8 DD5.6 ; 50.5,44.5 DD5.39 ; 53,25.1 53.2,25.1 53.71,25.61 DD4.8 ; v1(61.3,25.3) 61.315,25.315 61.315,27.235 DD4.2 ; DD11.4 63.15,34.35 63.4,34.6
  Top Layer w0.6: v1(34.4,46.4) C33.2 ; 36.4,29.1 v1(36.4,30.9) ; 41.6,43.7 v1(42.6,43.7) ; 46,40.2 v1(46,41) ; v1(46,48) 46,48.8 ; C28.2 47.9,35.975 47.9,34.8 48.5,34.2 v1(49.5,34.2) ; C23.2 50.6,25 50.723,25.123 51.423,25.123 v1(51.5,25.2) 51.577,25.123 52.752,25.123 52.776,25.1 53,25.1 ; C25.2@48.65,63.65 C25.2 50.6,64 51.4,64.8 56.825,64.8 57.177,64.449 57.177,63.477 v1(57.1,63.4) ; C29.2 51.692,54 51.892,54.2 v1(52,54.2) ; v1(49.8,44.5) 50.5,44.5 ; C35.2 C34.2 55.012,34.112 57.188,34.112 v1(57.2,34.1) ; C32.2 v1(57.1,46.5) ; C14.2 56.549,58 57.1,58.551 v1(57.1,63.4) ; C16.2 55,62.8 55.6,63.4 v1(57.1,63.4) ; 63.4,34.6 63.723,34.923 63.723,36.123 v1(63.8,36.2) ; v1(65.3,42.8) 65.35,42.75 65.35,40.925 C38.2 C39.2 ; C15.2 67.35,26.75 67.723,27.123 67.723,27.923 v1(67.8,28) ; C37.2 C36.2 67.925,30.95 69.85,30.95 v1(69.9,30.9)
  Top Layer w1: DD2.9@23.06,35.8 DD2.9 23.5,35.44 25.36,35.44 25.8,35 C8.2 C6.2 32,35 v1(32.1,35.1)
Общ_DRV: C10.2 C12.2 C13.2 C22.2 DD3.9 DD4.9 DD4.15 DD6.6 DD6.7 DD6.15 DD6.16 DD9.9 DD9.15 DD10.6 DD10.7 DD10.15 DD10.16 | length 39
  Top Layer w0.3: DD9.9 36.19,16.31 36.4,16.1 37.4,16.1 v1(37.5,16) 37.596,15.904 37.596,13.379 DD10.7 DD10.6 ; DD10.15 40.925,7.5 v1(42.7,7.5) ; DD9.15 43.855,17.955 43.855,15.845 v1(43.9,15.8) ; DD4.9 53.71,16.29 54.2,15.8 v1(55,15.8) 55,15.076 55.176,14.9 55.9,14.9 56.496,14.304 56.496,13.579 DD6.7 DD6.6 ; DD6.15 DD6.16 60.475,7.7 v1(61.7,7.7) ; DD4.15 61.33,16.35 61.8,15.88 v1(61.8,15.8)
  Top Layer w0.6: C22.2 48.55,19.05 48.55,16.85 v1(48.6,16.8) ; C13.2 65.7,16.808 v1(65.75,16.758)
  Top Layer w1: DD3.9 23.3,26.014 23.886,26.6 26.9,26.6 27.6,25.9 C12.2 29.112,25.887 C10.2@32.087,25.887 ; C10.2 C10.2@32.087,25.887 ; v1(32.1,27.4) 32.1,26.075 32,25.975 C10.2@32.087,25.887
Общ_RS: C2.2 C4.2 C21.1 C24.2 DD1.9 DD7.9 DD7.15 DD8.5 | length 30.3
  Top Layer w0.3: DD7.15 38.5,71.96 38.5,70.5 ; 46,74.3 46.08,74.22 DD7.9 ; v1(57.7,70.5) DD8.5
  Top Layer w0.6: DD1.9 v1(23.46,73.74) ; 38.5,70.5 38.523,70.477 38.523,69.477 v1(38.6,69.4) ; C21.1 v1(60.5,78.1)
  Top Layer w1: DD1.9 23.4,70.94 23.4,69.286 23.986,68.7 27.3,68.7 28.3,69.7 C4.2 C2.2 ; C24.2 v1(42.9,75.8) 44.5,75.8 46,74.3
pads on no net: DD1.2 DD1.6 DD1.7 DD2.2 DD2.6 DD2.7 DD3.2 DD3.6 DD3.7 DD5.14 DD5.15 DD5.16 DD5.19 DD5.23 DD5.30 DD5.31 DD5.32 DD5.33 DD5.34 DD5.35 DD5.40 DD5.41 DD5.42 DD5.43 DD5.44 DD6.17 DD7.6 DD7.11 DD10.17 DD11.1 DD11.5 DD11.7 DD11.8 XP5.
copper on no net:
  other v2: 38.15,9.85 39.25,9.85 40.35,9.85 57.05,10.05 58.15,10.05 59.25,10.05 38.15,10.95 39.25,10.95 40.35,10.95 57.05,11.15 58.15,11.15 59.25,11.15

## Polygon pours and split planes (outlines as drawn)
GND on Bottom Layer "GND_L02_P011" (solid, pour order 11): 0.8,72 11.9,72 11.9,52.2 13,51.1 28.1,51.1 28.7,50.5 28.7,41.9 28.2,41.4 14.3,41.4 12.4,39.5 12.4,5.8 15.2,3 74.6,3 72.444,0.844 cw(c70.648,2.64) 70.648,0.1 2.54,0.1 cw(c2.54,2.64) 0,2.64 0,71.2
GND on Bottom Layer "GND_L02_P014" (solid, pour order 14): 29,8 29,2 cw(c28.759,2.241) 28.759,1.9 20.7,1.9 20.7,8
no net on Bottom Layer "NONET_L02_P010" (solid, pour order 10): 42.3,10.4
Общ_DRV on Bottom Layer "Общ_DRV_L02_P009" (solid, pour order 9): 27,28 27,15 36.2,15 37.5,13.7 37.3,13.5 37.3,11.8 42.1,7 47,7 47,15.9 53.7,15.9 55.6,14 55.6,11.3 60.2,6.7 67,6.7 75,14.7 75,21.4 74.7,21.7 33.2,21.7 33.2,27.7 32.9,28
Общ on Bottom Layer "Общ_L02_P001" (solid, pour order 1): 20.4,36.4 20.4,31.5 20.9,31 34.6,31 35.4,30.2 35.4,24.6 73.4,24.6 75,26.2 75,61.7 71.8,64.9 35.1,64.9 34,63.8 34,37.7 33.3,37 21,37
no net on Bottom Layer "NONET_L02_P004" (solid, pour order 4): 33.6,15.9
Общ_RS on Bottom Layer "Общ_RS_L02_P000" (solid, pour order 0): 21.8,77.1 21.8,76.8 21.8,69.2 23,68 60.8,68 62,69.2 62,78.7 60.7,80 22.9,80 21.8,78.9
no net on Top Layer "NONET_L01_P012" (solid, pour order 12): 5,0 5,-1.3 ccw(c5.5,-1.3) 5.5,-1.8
NetDD6_10 on Top Layer "NETDD6_10_L01_P008" (solid, pour order 8): 49.037,10.388 56.737,10.388 56.737,6.988 49.737,6.988 48.937,7.788 48.937,10.347
NetDD6_8 on Top Layer "NETDD6_8_L01_P007" (solid, pour order 7): 49,15.4 54,15.4 55.2,14.2 56,14.2 56,11.7 49,11.7
NetDD10_10 on Top Layer "NETDD10_10_L01_P006" (solid, pour order 6): 30.9,10.3 30.9,7.1 31,7 37.8,7 37.7,7.1 37.7,10.3
NetDD10_8 on Top Layer "NETDD10_8_L01_P005" (solid, pour order 5): 30.9,11.4 30.9,16.2 35.4,16.2 37.2,14.4 37.2,11.4

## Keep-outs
Keep-Out Layer:
  the board outline again, w0.254

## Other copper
Bottom Layer:
  pour cut-out: 55.4,12.4 55.4,8.9 55.5,8.8 60.9,8.8 60.9,12.3 60.8,12.4
  pour cut-out: 36.6,12.2 41.9,12.2 41.9,8.5 41.8,8.6 36.5,8.6

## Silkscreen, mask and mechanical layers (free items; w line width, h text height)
Top Overlay:
  circle w0.254: c70,5 r3
  circle w0.254: c5,5 r3
  circle w0.254: c70,75 r3
  circle w0.254: c5,75 r3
